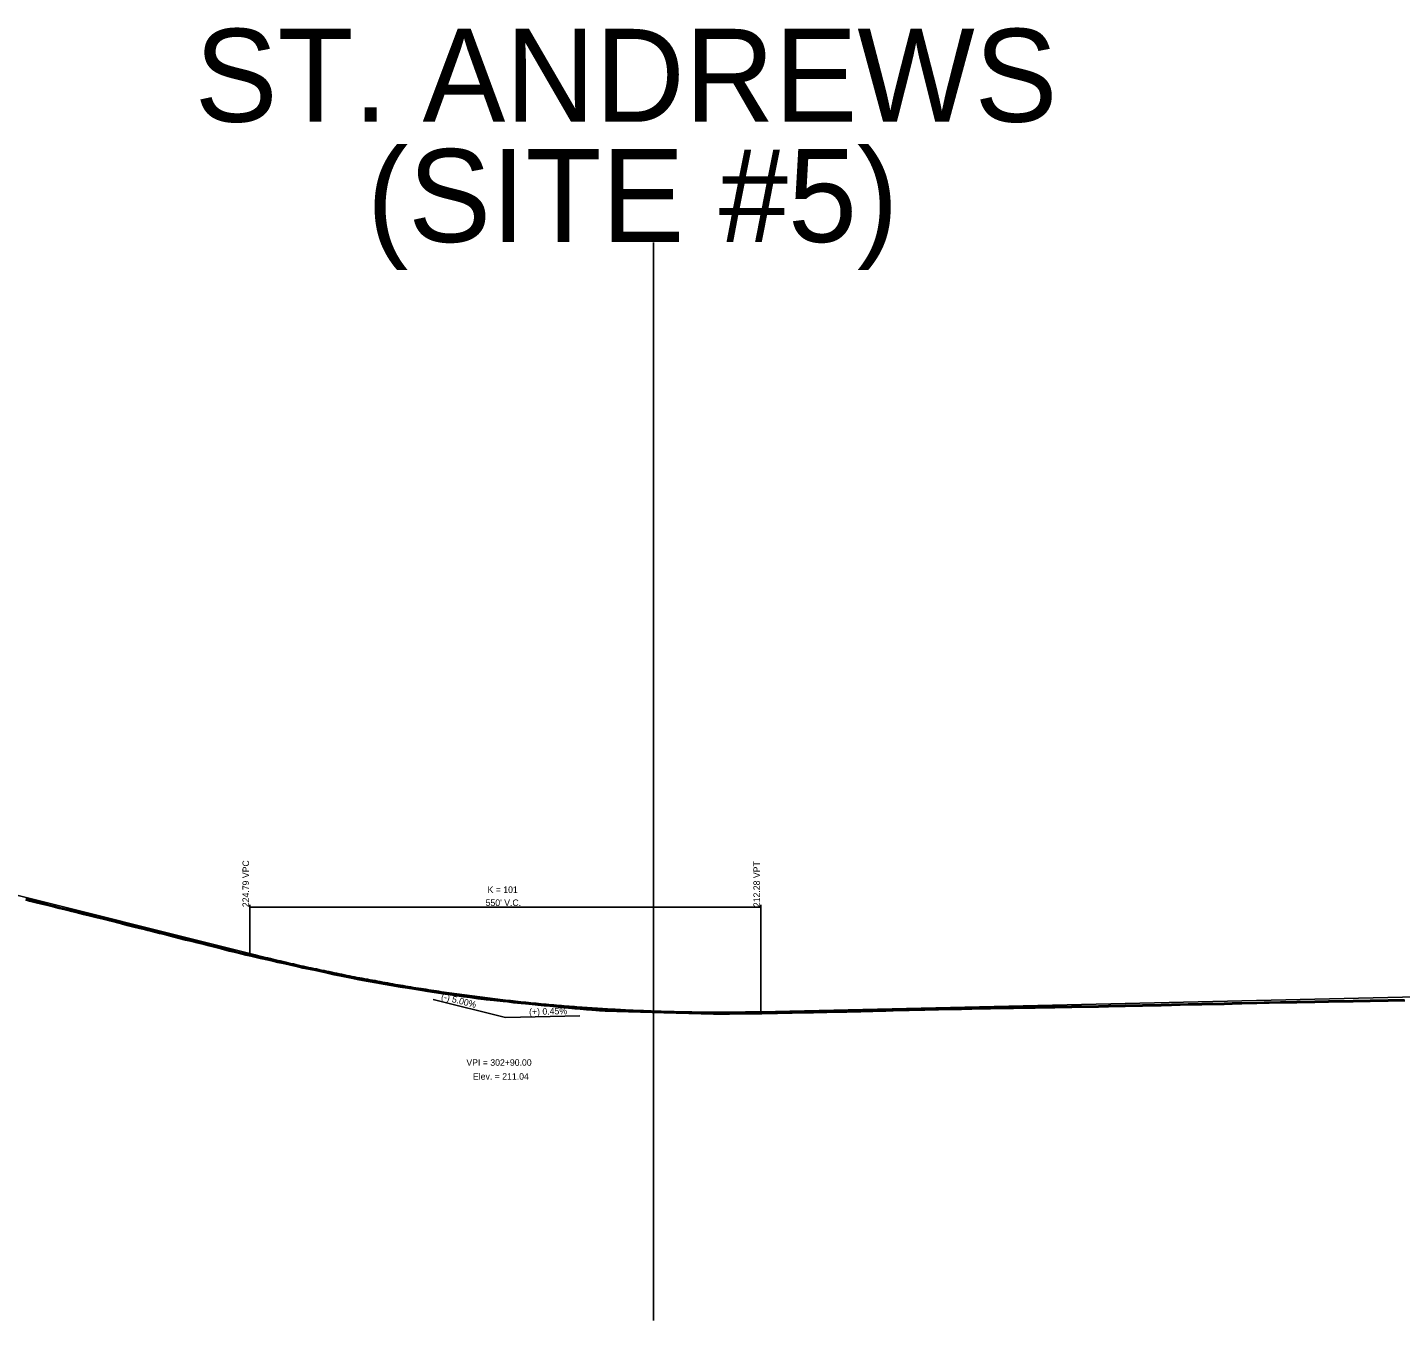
# Model space of a CAD drawing. Extents: x 1876258 to 1932803, y 754739 to 837911.
# Drawn here: x 1908139 to 1909617, y 830733 to 832125 of the extents above; entities that cross this region are included whole.
import ezdxf

# ---------------------------------------------------------------- set-up
doc = ezdxf.new("R2010")
doc.units = 0
for name, color, linetype in [('RD_DDB_GradeTX', 7, 'Continuous'), ('RD_DDB_Profile_EX', 7, 'Continuous'), ('RD_DDB_Profile_Lbl', 7, 'Continuous'), ('RD_DDB_Profile_PR', 7, 'Continuous'), ('RD_DDB_StripGrade', 7, 'Continuous'), ('RD_DDB_VCLbl', 7, 'Continuous'), ('RD_Sketch1', 7, 'Continuous')]:
    doc.layers.add(name, color=color, linetype=linetype)

msp = doc.modelspace()

# ---------------------------------------------------------------- linework, layer by layer
at = {"layer": 'RD_DDB_GradeTX'}
for p in [(1908575.5, 831078.9), (1908733.1, 831061.3)]:
    msp.add_line(p, (1908653.1, 831059.5), dxfattribs=at)
at = {"layer": 'RD_DDB_Profile_EX'}
for points in [[(1908136.6, 831185.9), (1908140.9, 831184.8), (1908146.6, 831183.3), (1908154.2, 831181.5), (1908159.2, 831180.2), (1908166.2, 831178.4), (1908172.9, 831176.8), (1908181, 831174.8), (1908186.4, 831173.6), (1908193.5, 831171.8), (1908199.1, 831170.4), (1908206.4, 831168.6), (1908212.4, 831167.1), (1908220.3, 831165.1), (1908227.3, 831163.3), (1908239.9, 831160.1), (1908246.1, 831158.6), (1908253, 831156.8), (1908259.3, 831155.3), (1908264.7, 831154), (1908268.1, 831153.2), (1908271.5, 831152.3), (1908280.6, 831150), (1908283, 831149.4), (1908288.5, 831148), (1908296.4, 831146), (1908302, 831144.6), (1908308.9, 831142.7), (1908315.8, 831141.1), (1908321.4, 831139.8), (1908328.8, 831137.9), (1908334.1, 831136.6), (1908341.5, 831134.6), (1908347.1, 831133.2), (1908355.7, 831131), (1908361.2, 831129.6), (1908368.2, 831128), (1908373.7, 831126.6), (1908379.1, 831125.4), (1908389.1, 831123), (1908394.7, 831121.7), (1908402.6, 831119.9), (1908408.2, 831118.7), (1908415.8, 831117.1), (1908421.8, 831115.8), (1908429.8, 831114), (1908435.2, 831112.7), (1908442.8, 831111.1), (1908448.6, 831109.9), (1908459.8, 831107.4), (1908464.2, 831106.4), (1908468.6, 831105.5), (1908476.4, 831103.8), (1908487.1, 831101.7), (1908495.2, 831100.1), (1908505.5, 831098.2), (1908513.8, 831096.7), (1908521.6, 831095.3), (1908529.8, 831093.9), (1908539.7, 831092.2), (1908547.8, 831090.9), (1908554.5, 831089.8), (1908561.1, 831088.7), (1908569.1, 831087.4), (1908576.5, 831086.3), (1908585.9, 831085), (1908593.7, 831083.9), (1908600.9, 831082.9), (1908607.9, 831081.8), (1908614.9, 831080.9), (1908623.6, 831079.7), (1908629.8, 831078.9), (1908632.5, 831078.6), (1908640.6, 831077.6), (1908650.8, 831076.6), (1908655.5, 831076.2), (1908662, 831075.4), (1908670, 831074.6), (1908674.9, 831074.1), (1908681.9, 831073.4), (1908687.9, 831072.8), (1908688.5, 831072.6), (1908694.8, 831072), (1908700.9, 831071.5)], [(1908700.9, 831071.5), (1908707.2, 831070.8), (1908716, 831069.9), (1908720.9, 831069.5), (1908727.9, 831068.8), (1908733.7, 831068.3), (1908740.3, 831067.7), (1908746.2, 831067.2), (1908754.5, 831066.7), (1908760.6, 831066.3), (1908823.8, 831064.4), (1908877, 831063.1), (1908886.1, 831063.2), (1908894.4, 831063.2), (1908903.3, 831063.3), (1908911.8, 831063.3), (1908919.4, 831063.4), (1908929.2, 831063.5), (1908938.4, 831063.6), (1908946, 831063.8), (1908955.6, 831064), (1908961.8, 831064.1), (1908970.6, 831064.4), (1908976.3, 831064.5), (1908984.9, 831064.6), (1908992, 831064.7), (1908999, 831064.8), (1909005.1, 831065), (1909012.9, 831065.2), (1909020.5, 831065.3), (1909028.3, 831065.5), (1909035.7, 831065.7), (1909041.9, 831065.8), (1909048.8, 831066), (1909057.6, 831066.2), (1909062.7, 831066.3), (1909070.5, 831066.6), (1909081.6, 831066.8), (1909087.9, 831067), (1909097.3, 831067.2), (1909104.7, 831067.4), (1909111.5, 831067.6), (1909119.2, 831067.8), (1909124, 831067.9), (1909135.5, 831068.1), (1909144.2, 831068.2), (1909155.2, 831068.4), (1909165.4, 831068.6), (1909175.3, 831068.8), (1909183.4, 831069), (1909190.7, 831069.1), (1909200, 831069.3), (1909207.5, 831069.4), (1909210.1, 831069.4), (1909216.8, 831069.5), (1909223.4, 831069.6), (1909231.3, 831069.8), (1909237.7, 831069.9), (1909244.7, 831070), (1909250.8, 831070.1), (1909257.5, 831070.2), (1909262.7, 831070.3), (1909268.9, 831070.5), (1909273.7, 831070.5), (1909282.5, 831070.6), (1909291.6, 831070.7), (1909302.4, 831071), (1909311.4, 831071.2), (1909320.4, 831071.3), (1909330.7, 831071.5), (1909339, 831071.7), (1909348.5, 831071.9), (1909359.1, 831072.1), (1909370.1, 831072.4), (1909379.3, 831072.7), (1909388, 831072.9), (1909398.1, 831073), (1909402.9, 831073.1), (1909413.5, 831073.3), (1909426.8, 831073.6), (1909435.4, 831073.8), (1909445.8, 831074.1), (1909462, 831074.5), (1909470, 831074.7), (1909475.1, 831074.8), (1909487.6, 831075.1), (1909494.2, 831075.2), (1909505, 831075.4), (1909513.3, 831075.5), (1909524.3, 831075.7), (1909532.3, 831075.8), (1909539.1, 831075.9), (1909549, 831076.2), (1909555, 831076.3), (1909565.5, 831076.4), (1909573.7, 831076.5), (1909584, 831076.7), (1909593.3, 831076.9), (1909603.5, 831077.1), (1909609.4, 831077.2), (1909621.2, 831077.4)]]:
    msp.add_lwpolyline(points, dxfattribs=at)
at = {"layer": 'RD_DDB_Profile_PR'}
for p, q in [((1908058.1, 831208.2), (1908378.1, 831128.2)), ((1908928.1, 831065.7), (1910073.1, 831091.5))]:
    msp.add_line(p, q, dxfattribs=at)
msp.add_spline([(1908378.1, 831128.2), (1908389.1, 831125.5), (1908400.1, 831122.9), (1908411.1, 831120.3), (1908422.1, 831117.7), (1908433.1, 831115.2), (1908444.1, 831112.8), (1908455.1, 831110.5), (1908466.1, 831108.2), (1908477.1, 831105.9), (1908488.1, 831103.7), (1908499.1, 831101.6), (1908510.1, 831099.6), (1908521.1, 831097.6), (1908532.1, 831095.6), (1908543.1, 831093.7), (1908554.1, 831091.9), (1908565.1, 831090.2), (1908576.1, 831088.5), (1908587.1, 831086.8), (1908598.1, 831085.2), (1908609.1, 831083.7), (1908620.1, 831082.3), (1908631.1, 831080.9), (1908642.1, 831079.5), (1908653.1, 831078.2), (1908664.1, 831077), (1908675.1, 831075.8), (1908686.1, 831074.7), (1908697.1, 831073.7), (1908708.1, 831072.7), (1908719.1, 831071.8), (1908730.1, 831070.9), (1908741.1, 831070.1), (1908752.1, 831069.4), (1908763.1, 831068.7), (1908774.1, 831068.1), (1908785.1, 831067.5), (1908796.1, 831067), (1908807.1, 831066.6), (1908818.1, 831066.2), (1908829.1, 831065.9), (1908840.1, 831065.6), (1908851.1, 831065.4), (1908862.1, 831065.3), (1908873.1, 831065.2), (1908884.1, 831065.2), (1908895.1, 831065.2), (1908906.1, 831065.3), (1908917.1, 831065.5), (1908928.1, 831065.7)], degree=3, dxfattribs=at)
at = {"layer": 'RD_DDB_VCLbl'}
for p, q in [((1908378.1, 831180.7), (1908378.1, 831128.2)), ((1908378.1, 831178.2), (1908928.1, 831178.2)), ((1908928.1, 831180.7), (1908928.1, 831065.7))]:
    msp.add_line(p, q, dxfattribs=at)
at = {"layer": 'RD_Sketch1'}
msp.add_line((1908812.7, 830733.3), (1908812.7, 831893.4), dxfattribs=at)
msp.add_lwpolyline([(1908136.9, 831187.1), (1908141.2, 831186), (1908146.9, 831184.5), (1908154.5, 831182.7), (1908159.5, 831181.4), (1908166.5, 831179.7), (1908173.2, 831178), (1908181.3, 831176.1), (1908186.7, 831174.8), (1908193.8, 831173), (1908199.4, 831171.6), (1908206.7, 831169.8), (1908212.7, 831168.3), (1908220.6, 831166.3), (1908227.6, 831164.5), (1908240.2, 831161.3), (1908246.5, 831159.8), (1908253.3, 831158.1), (1908259.6, 831156.5), (1908265, 831155.2), (1908268.3, 831154.4), (1908271.8, 831153.5), (1908280.9, 831151.3), (1908283.3, 831150.7), (1908288.8, 831149.2), (1908296.7, 831147.2), (1908302.3, 831145.8), (1908309.2, 831144), (1908316, 831142.3), (1908321.7, 831141), (1908329.1, 831139.1), (1908334.4, 831137.8), (1908341.8, 831135.8), (1908347.4, 831134.4), (1908356, 831132.2), (1908361.5, 831130.8), (1908368.5, 831129.2), (1908374, 831127.9), (1908379.4, 831126.6), (1908389.3, 831124.2), (1908395, 831123), (1908402.9, 831121.2), (1908408.4, 831119.9), (1908416.1, 831118.3), (1908422.1, 831117.1), (1908430.1, 831115.2), (1908435.5, 831113.9), (1908443, 831112.4), (1908448.9, 831111.1), (1908460, 831108.6), (1908464.5, 831107.6), (1908468.9, 831106.7), (1908476.6, 831105), (1908487.4, 831102.9), (1908495.4, 831101.4), (1908505.7, 831099.4), (1908514, 831097.9), (1908521.8, 831096.5), (1908530, 831095.1), (1908539.9, 831093.5), (1908548, 831092.2), (1908554.7, 831091), (1908561.3, 831089.9), (1908569.3, 831088.6), (1908576.7, 831087.5), (1908586.1, 831086.2), (1908593.8, 831085.1), (1908601, 831084.1), (1908608.1, 831083.1), (1908615.1, 831082.1), (1908623.7, 831080.9), (1908629.9, 831080.1), (1908632.6, 831079.9), (1908640.8, 831078.9), (1908650.9, 831077.8), (1908655.7, 831077.4), (1908662.1, 831076.6), (1908670.1, 831075.8), (1908675, 831075.4), (1908682, 831074.7), (1908688.2, 831074), (1908688.7, 831073.8), (1908695, 831073.3), (1908701, 831072.7), (1908707.3, 831072), (1908716.1, 831071.2), (1908721.1, 831070.7), (1908728, 831070.1), (1908733.8, 831069.5), (1908740.4, 831069), (1908746.3, 831068.5), (1908754.6, 831067.9), (1908760.7, 831067.5), (1908823.8, 831065.7), (1908877, 831064.3), (1908886.1, 831064.4), (1908894.4, 831064.4), (1908903.3, 831064.5), (1908911.8, 831064.6), (1908919.4, 831064.7), (1908929.2, 831064.8), (1908938.3, 831064.9), (1908946, 831065.1), (1908955.5, 831065.3), (1908961.8, 831065.4), (1908970.6, 831065.6), (1908976.2, 831065.7), (1908984.9, 831065.9), (1908991.9, 831066), (1908998.9, 831066.1), (1909005, 831066.3), (1909012.9, 831066.4), (1909020.5, 831066.6), (1909028.3, 831066.7), (1909035.6, 831066.9), (1909041.9, 831067.1), (1909048.8, 831067.2), (1909057.6, 831067.5), (1909062.6, 831067.6), (1909070.5, 831067.8), (1909081.6, 831068.1), (1909087.8, 831068.2), (1909097.3, 831068.5), (1909104.6, 831068.7), (1909111.4, 831068.8), (1909119.1, 831069.1), (1909124, 831069.2), (1909135.4, 831069.3), (1909144.2, 831069.5), (1909155.2, 831069.6), (1909165.3, 831069.8), (1909175.3, 831070), (1909183.4, 831070.2), (1909190.6, 831070.4), (1909200, 831070.6), (1909207.5, 831070.6), (1909210.1, 831070.6), (1909216.8, 831070.7), (1909223.4, 831070.8), (1909231.2, 831071), (1909237.7, 831071.1), (1909244.6, 831071.2), (1909250.8, 831071.3), (1909257.5, 831071.4), (1909262.6, 831071.5), (1909268.8, 831071.7), (1909273.6, 831071.7), (1909282.4, 831071.8), (1909291.6, 831072), (1909302.4, 831072.3), (1909311.4, 831072.4), (1909320.4, 831072.6), (1909330.7, 831072.8), (1909339, 831072.9), (1909348.5, 831073.1), (1909359.1, 831073.4), (1909370, 831073.7), (1909379.3, 831073.9), (1909388, 831074.1), (1909398.1, 831074.3), (1909402.9, 831074.4), (1909413.4, 831074.5), (1909426.7, 831074.8), (1909435.4, 831075.1), (1909445.8, 831075.4), (1909462, 831075.7), (1909470, 831075.9), (1909475, 831076.1), (1909487.6, 831076.3), (1909494.2, 831076.4), (1909505, 831076.7), (1909513.3, 831076.7), (1909524.3, 831076.9), (1909532.3, 831077), (1909539.1, 831077.2), (1909549, 831077.5), (1909555, 831077.5), (1909565.5, 831077.6), (1909573.7, 831077.8), (1909584, 831078), (1909593.3, 831078.1), (1909603.4, 831078.3), (1909609.4, 831078.5), (1909621.1, 831078.6)], dxfattribs=at)

# ---------------------------------------------------------------- texts
at = {"layer": 'RD_DDB_GradeTX'}
for s, rotation, p in [('(-) 5.00%', 345.9638, (1908583.4, 831079)), ('(+) 0.45%', 1.2894, (1908678.7, 831062.1))]:
    msp.add_text(s, height=7, rotation=rotation, dxfattribs=at).set_placement(p)
at = {"layer": 'RD_DDB_Profile_Lbl'}
for s, p in [('VPI = 302+90.00', (1908611.1, 831007.5)), ('Elev. = 211.04', (1908618.2, 830992.5))]:
    msp.add_text(s, height=7, dxfattribs=at).set_placement(p)
at = {"layer": 'RD_DDB_StripGrade'}
for s, p in [('224.79 VPC', (1908377.1, 831178.2)), ('212.28 VPT', (1908927.1, 831178.2))]:
    msp.add_text(s, height=7, rotation=90, dxfattribs=at).set_placement(p)
at = {"layer": 'RD_DDB_VCLbl'}
for s, p in [("550' V.C.", (1908631.8, 831179.5)), ('K = 101', (1908633.9, 831193.5))]:
    msp.add_text(s, height=7, dxfattribs=at).set_placement(p)
at = {"layer": 'RD_Sketch1'}
for s, p in [('ST. ANDREWS', (1908318.7, 832023.5)), ('(SITE #5)', (1908504, 831894.1))]:
    msp.add_text(s, height=100, dxfattribs=at).set_placement(p)

doc.saveas('drawing.dxf')
